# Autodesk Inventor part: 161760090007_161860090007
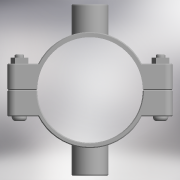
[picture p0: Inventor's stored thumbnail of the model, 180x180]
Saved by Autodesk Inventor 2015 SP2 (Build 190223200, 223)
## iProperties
Created: 2017-05
Part Number: 161760090007_161860090007
Material: Generic
Description: PLASSON DOUBLE SADDLE 90-3/4"
Document SubType Name: Modeling
Designer: KIM
Density: 1 g/cm^3
Appearance: Default
Author: KIM
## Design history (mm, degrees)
derived "16176.ipt"
feature "Solid1::16176.ipt"
feature "Solid2::16176.ipt"
tag "TaggingFeature1"
body "Solid1"
body "Solid2"
other parameters: "d0" = 99, "d1" = 141, "d2" = 45, "d4" = 105, "d5" = 0, "d6" = 7.05, "d7" = 141, "d8" = 0.1, "d10" = 0, "d11" = 0.9, "d20" = 0.9, "d23" = 0.9, "d36" = 13, "d37" = 10.4, "d38" = 53, "d39" = 0, "d40" = 3, "d41" = 5, "d42" = 0, "d43" = 8, "d44" = 3, "d45" = 0, "d46" = 0.9, "d52" = 24.117, "d53" = 19, "d54" = 0, "d57" = 0, "d58" = 97.2, "d60" = 0, "d62" = 13, "d63" = 10.4, "d66" = 84.2, "d67" = 146, "d68" = 31.3521, "d69" = 24.117, "d70" = 19, "d71" = 0, "d74" = 0, "d75" = 0.9, "G_" = 24.117, "A_" = 73, "L_" = 141, "L_1" = 105, "l_2" = 19
